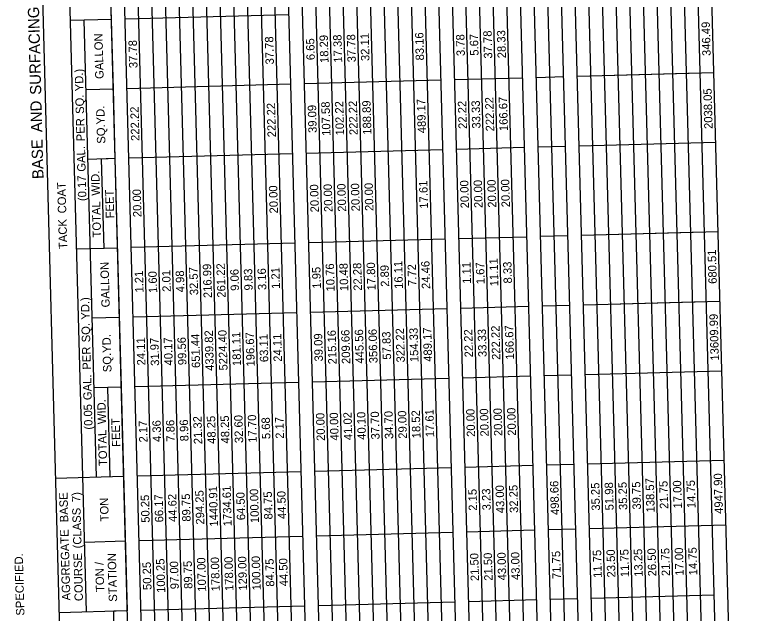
# Model space of a CAD drawing. Extents: x 1930091 to 1931962, y 596452 to 607874.
# Drawn here: x 1930670 to 1931189, y 601827 to 602254 of the extents above; entities that cross this region are included whole.
import ezdxf

# ---------------------------------------------------------------- set-up
doc = ezdxf.new("R2010")
doc.units = 0
doc.layers.add('Default', color=7, linetype='Continuous')

msp = doc.modelspace()

# ---------------------------------------------------------------- linework, layer by layer
at = {"layer": 'Default'}
for p, q in [((1931121.17, 601449.61), (1931080.28, 602972.5)), ((1931130.91, 601449.87), (1931090.03, 602972.76)), ((1931140.66, 601450.14), (1931099.78, 602973.02)), ((1931150.4, 601450.4), (1931109.52, 602973.29)), ((1931160.15, 601450.66), (1931119.27, 602973.55)), ((1931169.9, 601450.92), (1931129.02, 602973.81)), ((1931179.64, 601451.18), (1931138.76, 602974.07)), ((1931189.39, 601451.44), (1931148.51, 602974.33)), ((1930926.24, 601444.38), (1930885.35, 602967.27)), ((1930935.98, 601444.64), (1930895.1, 602967.53)), ((1930945.73, 601444.9), (1930904.85, 602967.79)), ((1930955.48, 601445.16), (1930914.59, 602968.05)), ((1930965.22, 601445.43), (1930924.34, 602968.32)), ((1930974.97, 601445.69), (1930934.09, 602968.58)), ((1930984.71, 601445.95), (1930943.83, 602968.84)), ((1930994.46, 601446.21), (1930953.58, 602969.1)), ((1930994.46, 601446.21), (1930953.58, 602969.1)), ((1931004.21, 601446.47), (1930963.33, 602969.36)), ((1931013.95, 601446.73), (1930973.07, 602969.62)), ((1931023.7, 601447), (1930982.82, 602969.89)), ((1931033.45, 601447.26), (1930992.57, 602970.15)), ((1931043.19, 601447.52), (1931002.31, 602970.41)), ((1931052.94, 601447.78), (1931012.06, 602970.67)), ((1931052.94, 601447.78), (1931012.06, 602970.67)), ((1931062.69, 601448.04), (1931021.81, 602970.93)), ((1931072.43, 601448.3), (1931031.55, 602971.19)), ((1931082.18, 601448.57), (1931041.3, 602971.46)), ((1931082.18, 601448.57), (1931041.3, 602971.46)), ((1931091.93, 601448.83), (1931051.05, 602971.72)), ((1931101.67, 601449.09), (1931060.79, 602971.98)), ((1931111.42, 601449.35), (1931070.54, 602972.24)), ((1930720.88, 601827.54), (1930690.43, 602962.04)), ((1930760.55, 601439.93), (1930719.66, 602962.82)), ((1930770.29, 601440.19), (1930729.41, 602963.08)), ((1930780.04, 601440.46), (1930739.16, 602963.34)), ((1930789.78, 601440.72), (1930748.9, 602963.61)), ((1930799.53, 601440.98), (1930758.65, 602963.87)), ((1930809.28, 601441.24), (1930768.4, 602964.13)), ((1930819.02, 601441.5), (1930778.14, 602964.39)), ((1930828.77, 601441.76), (1930787.89, 602964.65)), ((1930838.52, 601442.03), (1930797.64, 602964.91)), ((1930848.26, 601442.29), (1930807.38, 602965.18)), ((1930858.01, 601442.55), (1930817.13, 602965.44)), ((1930867.76, 601442.81), (1930826.88, 602965.7)), ((1930877.5, 601443.07), (1930836.62, 602965.96)), ((1930887.25, 601443.33), (1930846.37, 602966.22)), ((1930887.25, 601443.33), (1930846.37, 602966.22)), ((1930897, 601443.6), (1930856.12, 602966.48)), ((1930906.74, 601443.86), (1930865.86, 602966.75)), ((1930916.49, 601444.12), (1930875.61, 602967.01)), ((1930711.81, 601438.62), (1930670.93, 602961.51)), ((1930740.11, 602201.13), (1930736.11, 602350.25)), ((1930738.78, 602250.84), (1930709.54, 602250.06)), ((1930728.05, 601923.81), (1930719.28, 602250.32)), ((1930865.48, 602254.24), (1930748.52, 602251.1)), ((1930865.48, 602254.24), (1930748.52, 602251.1)), ((1931032.51, 602208.98), (1930983.77, 602207.67)), ((1931032.51, 602208.98), (1930983.77, 602207.67)), ((1931061.75, 602209.77), (1931042.25, 602209.24)), ((1931061.75, 602209.77), (1931042.25, 602209.24)), ((1931168.96, 602212.65), (1931071.49, 602210.03)), ((1931159.21, 602212.38), (1931071.49, 602210.03)), ((1930866.82, 602204.53), (1930749.86, 602201.39)), ((1930866.82, 602204.53), (1930749.86, 602201.39)), ((1930974.03, 602207.41), (1930876.56, 602204.8)), ((1930974.03, 602207.41), (1930876.56, 602204.8)), ((1930740.11, 602201.13), (1930720.62, 602200.61)), ((1930741.45, 602151.43), (1930740.11, 602201.13)), ((1931170.29, 602162.94), (1931072.83, 602160.32)), ((1931170.29, 602162.94), (1931072.83, 602160.32)), ((1930975.36, 602157.71), (1930877.9, 602155.09)), ((1930975.36, 602157.71), (1930877.9, 602155.09)), ((1931033.84, 602159.28), (1930985.11, 602157.97)), ((1931033.84, 602159.28), (1930985.11, 602157.97)), ((1931063.08, 602160.06), (1931043.59, 602159.54)), ((1931063.08, 602160.06), (1931043.59, 602159.54)), ((1930741.45, 602151.43), (1930721.95, 602150.9)), ((1930741.45, 602151.43), (1930731.7, 602151.16)), ((1930733.41, 602087.32), (1930731.7, 602151.16)), ((1930745.83, 601988.17), (1930741.45, 602151.43)), ((1930868.15, 602154.83), (1930751.19, 602151.69)), ((1930868.15, 602154.83), (1930751.19, 602151.69)), ((1931172.01, 602099.1), (1931074.54, 602096.48)), ((1930977.08, 602093.87), (1930879.61, 602091.25)), ((1930977.08, 602093.87), (1930879.61, 602091.25)), ((1931035.55, 602095.44), (1930986.82, 602094.13)), ((1931035.55, 602095.44), (1930986.82, 602094.13)), ((1931064.79, 602096.22), (1931045.3, 602095.7)), ((1931064.79, 602096.22), (1931045.3, 602095.7)), ((1931162.26, 602098.84), (1931074.54, 602096.48)), ((1930869.86, 602090.99), (1930752.91, 602087.85)), ((1930869.86, 602090.99), (1930752.91, 602087.85)), ((1930743.16, 602087.59), (1930713.92, 602086.8)), ((1931173.34, 602049.39), (1931075.87, 602046.77)), ((1931163.59, 602049.13), (1931075.87, 602046.77)), ((1930978.41, 602044.16), (1930880.94, 602041.54)), ((1930978.41, 602044.16), (1930880.94, 602041.54)), ((1931036.89, 602045.73), (1930988.16, 602044.42)), ((1931036.89, 602045.73), (1930988.16, 602044.42)), ((1931066.13, 602046.51), (1931046.64, 602045.99)), ((1931066.13, 602046.51), (1931046.64, 602045.99)), ((1930744.49, 602037.88), (1930725, 602037.36)), ((1930871.2, 602041.28), (1930754.24, 602038.14)), ((1930871.2, 602041.28), (1930754.24, 602038.14)), ((1931038.22, 601996.02), (1930989.49, 601994.71)), ((1931038.22, 601996.02), (1930989.49, 601994.71)), ((1931067.46, 601996.81), (1931047.97, 601996.28)), ((1931067.46, 601996.81), (1931047.97, 601996.28)), ((1931174.67, 601999.68), (1931077.21, 601997.07)), ((1931174.67, 601999.68), (1931077.21, 601997.07)), ((1930872.53, 601991.57), (1930755.57, 601988.43)), ((1930872.53, 601991.57), (1930755.57, 601988.43)), ((1930979.74, 601994.45), (1930882.28, 601991.84)), ((1930979.74, 601994.45), (1930882.28, 601991.84)), ((1930745.83, 601988.17), (1930726.34, 601987.65)), ((1930745.83, 601988.17), (1930736.08, 601987.91)), ((1930737.8, 601924.07), (1930736.08, 601987.91)), ((1930750.12, 601828.33), (1930745.83, 601988.17)), ((1931069.18, 601932.97), (1931049.68, 601932.44)), ((1931069.18, 601932.97), (1931049.68, 601932.44)), ((1931176.39, 601935.84), (1931078.92, 601933.23)), ((1931176.39, 601935.84), (1931078.92, 601933.23)), ((1930874.25, 601927.73), (1930757.29, 601924.59)), ((1930874.25, 601927.73), (1930757.29, 601924.59)), ((1930981.46, 601930.61), (1930883.99, 601928)), ((1930981.46, 601930.61), (1930883.99, 601928)), ((1931039.94, 601932.18), (1930991.2, 601930.87)), ((1931039.94, 601932.18), (1930991.2, 601930.87)), ((1930747.54, 601924.33), (1930698.81, 601923.02)), ((1931041.18, 601885.89), (1930992.45, 601884.58)), ((1931041.18, 601885.89), (1930992.45, 601884.58)), ((1931070.42, 601886.67), (1931050.93, 601886.15)), ((1931070.42, 601886.67), (1931050.93, 601886.15)), ((1931177.63, 601889.55), (1931080.17, 601886.93)), ((1931177.63, 601889.55), (1931080.17, 601886.93)), ((1930875.49, 601881.44), (1930758.53, 601878.3)), ((1930875.49, 601881.44), (1930758.53, 601878.3)), ((1930982.7, 601884.32), (1930885.24, 601881.7)), ((1930982.7, 601884.32), (1930885.24, 601881.7)), ((1930748.78, 601878.04), (1930719.55, 601877.25)), ((1931169.22, 601839.58), (1931081.5, 601837.23)), ((1931169.22, 601839.58), (1931081.5, 601837.23)), ((1930984.03, 601834.61), (1930886.57, 601831.99)), ((1930984.03, 601834.61), (1930886.57, 601831.99)), ((1931042.51, 601836.18), (1930993.78, 601834.87)), ((1931042.51, 601836.18), (1930993.78, 601834.87)), ((1931071.75, 601836.96), (1931052.26, 601836.44)), ((1931071.75, 601836.96), (1931052.26, 601836.44)), ((1930876.82, 601831.73), (1930759.87, 601828.59)), ((1930876.82, 601831.73), (1930759.87, 601828.59)), ((1930750.12, 601828.33), (1930701.39, 601827.02)), ((1930750.12, 601828.33), (1930740.37, 601828.07)), ((1930741.71, 601778.36), (1930740.37, 601828.07))]:
    msp.add_line(p, q, dxfattribs=at)

# ---------------------------------------------------------------- texts
for s, height, p in [(' SURFACING', 8, (1930688.7, 602194.19)), ('346.49', 6, (1931166.75, 602224.83)), ('GALLON', 6, (1930733.16, 602208.45)), ('18.29', 6, (1930893.79, 602219.83)), ('17.38', 6, (1930903.54, 602220.09)), ('37.78', 6, (1930913.28, 602220.35)), ('32.11', 6, (1930923.01, 602221.2)), ('83.16', 6, (1930962.02, 602221.66)), ('3.78', 6, (1930991.19, 602224.77)), ('5.67', 6, (1931000.94, 602225.04)), ('37.78', 6, (1931010.75, 602222.97)), ('28.33', 6, (1931020.49, 602223.23)), ('37.78', 6, (1930757.34, 602216.16)), ('37.78', 6, (1930854.8, 602218.78)), ('6.65', 6, (1930883.98, 602221.88)), (' YD.)', 6, (1930718.83, 602197.41)), ('2038.05', 6, (1931168.15, 602172.73)), (' SQ.', 6, (1930719.26, 602181.23)), ('188.89', 6, (1930924.43, 602168.58)), ('489.17', 6, (1930963.41, 602169.63)), ('33.33', 6, (1931002.34, 602173)), ('222.22', 6, (1931012.14, 602170.97)), ('166.67', 6, (1931021.89, 602171.2)), (' AND', 8, (1930689.42, 602167.43)), ('SQ.YD.', 6, (1930734.4, 602162.18)), ('222.22', 6, (1930758.74, 602164.16)), ('222.22', 6, (1930856.2, 602166.78)), ('39.09', 6, (1930885.38, 602169.86)), ('107.58', 6, (1930895.19, 602167.79)), ('102.22', 6, (1930904.93, 602168.09)), ('222.22', 6, (1930914.68, 602168.35)), ('22.22', 6, (1930992.59, 602172.77)), (' PER', 6, (1930719.79, 602161.7)), ('BASE', 8, (1930690.24, 602136.94)), (' GAL.', 6, (1930720.37, 602139.94)), (' WID.', 6, (1930730.58, 602122.85)), ('(0.17', 6, (1930720.87, 602121.21)), ('17.61', 6, (1930964.86, 602115.76)), ('20.00', 6, (1930994.11, 602115.98)), ('20.00', 6, (1931003.86, 602116.24)), ('20.00', 6, (1931013.61, 602116.5)), ('20.00', 6, (1931023.35, 602116.76)), (' COAT', 6, (1930706.54, 602110.16)), ('20.00', 6, (1930857.66, 602112.32)), ('20.00', 6, (1930886.9, 602113.1)), ('20.00', 6, (1930896.65, 602113.36)), ('20.00', 6, (1930906.39, 602113.62)), ('20.00', 6, (1930916.14, 602113.89)), ('20.00', 6, (1930925.89, 602114.15)), ('FEET', 6, (1930740.71, 602108.83)), ('20.00', 6, (1930760.2, 602109.7)), ('TOTAL', 6, (1930731.33, 602095.17)), ('TACK', 6, (1930707.17, 602086.89)), ('680.51', 6, (1931171.12, 602062.06)), ('11.11', 6, (1931015.11, 602060.3)), ('GALLON', 6, (1930737.55, 602045.2)), ('32.57', 6, (1930800.71, 602053.96)), ('216.99', 6, (1930810.52, 602051.89)), ('261.22', 6, (1930820.26, 602052.19)), ('1.21', 6, (1930859.11, 602058.44)), ('1.95', 6, (1930888.36, 602058.62)), ('10.76', 6, (1930898.17, 602056.58)), ('10.48', 6, (1930907.92, 602056.84)), ('22.28', 6, (1930917.67, 602057.1)), ('17.80', 6, (1930927.41, 602057.37)), ('2.89', 6, (1930937.1, 602059.95)), ('16.11', 6, (1930946.89, 602058.47)), ('7.72', 6, (1930956.59, 602060.51)), ('24.46', 6, (1930966.4, 602058.41)), ('1.11', 6, (1930995.56, 602062.1)), ('1.67', 6, (1931005.32, 602061.79)), ('8.33', 6, (1931024.81, 602062.31)), ('1.21', 6, (1930761.64, 602055.83)), ('1.60', 6, (1930771.41, 602055.52)), ('2.01', 6, (1930781.14, 602056.35)), ('4.98', 6, (1930790.9, 602056.02)), ('9.06', 6, (1930829.88, 602057.08)), ('9.83', 6, (1930839.63, 602057.34)), ('3.16', 6, (1930849.38, 602057.6)), (' YD.)', 6, (1930723.21, 602034.22)), ('13609.99', 6, (1931172.6, 602007.21)), (' SQ.', 6, (1930723.64, 602018.03)), ('222.22', 6, (1931016.53, 602007.71)), ('166.67', 6, (1931026.27, 602007.94)), ('651.44', 6, (1930802.1, 602001.94)), ('4339.82', 6, (1930811.91, 601999.89)), ('5224.40', 6, (1930821.66, 602000.13)), ('181.11', 6, (1930831.33, 602003.29)), ('196.67', 6, (1930841.09, 602002.97)), ('39.09', 6, (1930889.76, 602006.6)), ('215.16', 6, (1930899.57, 602004.54)), ('209.66', 6, (1930909.32, 602004.8)), ('445.56', 6, (1930919.06, 602005.07)), ('356.06', 6, (1930928.81, 602005.33)), ('57.83', 6, (1930938.49, 602007.92)), ('322.22', 6, (1930948.3, 602005.88)), ('154.33', 6, (1930958.05, 602006.11)), ('489.17', 6, (1930967.79, 602006.37)), ('22.22', 6, (1930996.97, 602009.52)), ('33.33', 6, (1931006.72, 602009.75)), ('SQ.YD.', 6, (1930738.79, 601998.93)), ('24.11', 6, (1930763.04, 602003.79)), ('31.97', 6, (1930772.8, 602003.47)), ('40.17', 6, (1930782.55, 602003.73)), ('99.56', 6, (1930792.3, 602003.99)), ('63.11', 6, (1930850.76, 602006.14)), ('24.11', 6, (1930860.51, 602006.41)), (' PER', 6, (1930724.17, 601998.51)), (' GAL.', 6, (1930724.75, 601976.74)), ('(0.05', 6, (1930725.26, 601957.9)), (' WID.', 6, (1930734.97, 601959.6)), ('20.00', 6, (1930891.28, 601949.85)), ('40.00', 6, (1930901.03, 601950.11)), ('41.02', 6, (1930910.78, 601950.39)), ('40.10', 6, (1930920.52, 601950.63)), ('37.70', 6, (1930930.27, 601950.89)), ('34.70', 6, (1930940.02, 601951.16)), ('29.00', 6, (1930949.76, 601951.42)), ('18.52', 6, (1930959.51, 601951.7)), ('17.61', 6, (1930969.24, 601952.51)), ('20.00', 6, (1930998.5, 601952.73)), ('20.00', 6, (1931008.24, 601952.99)), ('20.00', 6, (1931017.99, 601953.25)), ('20.00', 6, (1931027.73, 601953.51)), ('FEET', 6, (1930745.1, 601945.58)), ('2.17', 6, (1930764.52, 601948.76)), ('4.36', 6, (1930774.26, 601949.03)), ('7.86', 6, (1930784.01, 601949.29)), ('8.96', 6, (1930793.76, 601949.55)), ('21.32', 6, (1930803.57, 601947.51)), ('48.25', 6, (1930813.31, 601947.72)), ('48.25', 6, (1930823.06, 601947.98)), ('32.60', 6, (1930832.81, 601948.28)), ('17.70', 6, (1930842.55, 601948.54)), ('5.68', 6, (1930852.24, 601951.11)), ('2.17', 6, (1930861.98, 601951.38)), ('TOTAL', 6, (1930735.71, 601931.92)), ('138.57', 6, (1931126.74, 601898.72)), ('4947.90', 6, (1931175.54, 601897.71)), ('1440.91', 6, (1930814.9, 601888.6)), ('1734.61', 6, (1930824.65, 601888.86)), ('43.00', 6, (1931019.47, 601898.18)), ('32.25', 6, (1931029.21, 601898.41)), ('498.66', 6, (1931058.52, 601896.89)), ('35.25', 6, (1931087.69, 601899.98)), ('51.98', 6, (1931097.44, 601900.26)), ('35.25', 6, (1931107.19, 601900.5)), ('39.75', 6, (1931116.93, 601900.76)), ('21.75', 6, (1931136.43, 601901.29)), ('17.00', 6, (1931146.17, 601901.58)), ('14.75', 6, (1931155.92, 601901.81)), (' BASE', 6, (1930707.96, 601889.45)), (' 7)', 6, (1930716.58, 601903.93)), ('89.75', 6, (1930795.3, 601892.13)), ('294.25', 6, (1930805.11, 601890.06)), ('64.50', 6, (1930834.28, 601893.21)), ('100.00', 6, (1930844.09, 601891.14)), ('84.75', 6, (1930853.78, 601893.7)), ('44.50', 6, (1930863.52, 601894)), ('2.15', 6, (1930999.91, 601899.95)), ('3.23', 6, (1931009.66, 601900.24)), ('TON', 6, (1930736.77, 601892.36)), ('50.25', 6, (1930766.06, 601891.34)), ('66.17', 6, (1930775.8, 601891.63)), ('44.62', 6, (1930785.55, 601891.92)), (' (CLASS', 6, (1930717.47, 601870.82)), ('AGGREGATE', 6, (1930709.4, 601835.84)), ('71.75', 6, (1931059.74, 601851.19)), ('11.75', 6, (1931088.98, 601851.98)), ('23.50', 6, (1931098.73, 601852.27)), ('11.75', 6, (1931108.47, 601852.5)), ('13.25', 6, (1931118.22, 601852.76)), ('26.50', 6, (1931127.97, 601853.06)), ('21.75', 6, (1931137.71, 601853.29)), ('17.00', 6, (1931147.46, 601853.58)), ('14.75', 6, (1931157.21, 601853.81)), (' SPECIFIED.', 6, (1930676.64, 601822.79)), ('COURSE', 6, (1930718.42, 601835.38)), ('STATION', 6, (1930742.81, 601834.94)), ('100.25', 6, (1930777.16, 601841.28)), ('107.00', 6, (1930806.39, 601842.09)), ('178.00', 6, (1930816.14, 601842.36)), ('178.00', 6, (1930825.89, 601842.62)), ('129.00', 6, (1930835.63, 601842.88)), ('100.00', 6, (1930845.38, 601843.14)), ('84.75', 6, (1930855.07, 601845.7)), ('44.50', 6, (1930864.81, 601845.99)), ('21.50', 6, (1931001.26, 601849.66)), ('21.50', 6, (1931011.01, 601849.92)), ('43.00', 6, (1931020.76, 601850.18)), ('43.00', 6, (1931030.5, 601850.44)), (' /', 6, (1930733.17, 601858.93)), ('50.25', 6, (1930767.35, 601843.34)), ('97.00', 6, (1930786.84, 601843.9)), ('89.75', 6, (1930796.59, 601844.13)), ('TON', 6, (1930733.62, 601841.91))]:
    msp.add_text(s, height=height, rotation=91.5377, dxfattribs=at).set_placement(p)

doc.saveas('drawing.dxf')
